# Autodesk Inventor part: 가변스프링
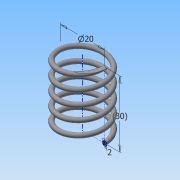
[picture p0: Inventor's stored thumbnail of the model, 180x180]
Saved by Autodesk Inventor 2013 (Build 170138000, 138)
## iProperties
Created: 2019-01
Part Number: 가변스프링
Material: Generic
Document SubType Name: Modeling
Designer: Administrator
Density: 1 g/cm^3
Author: Administrator
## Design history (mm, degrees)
sketch "스케치1"
  geometry: L1 (0, 0)-(10, 0); L2 (10, 0)-(10, 18.7); L3 (10, 18.7)-(0, 18.7); L4 (0, 18.7)-(0, 0); C1 r 1 at (10, 0)
  constraints: 8 end point, 2 parallel, 1 centre point, 1 coincident, 1 horizontal, 1 perpendicular
  dimensions: "d0" = 20 diameter of L2 L4; "d2" = 18.7 distance of L1.end L2.end (derived); "d3" = 2 diameter of C1
feature "코일1" pitch "d4" = 10; turns "d6" = 5; dims "d5" = 18.7 (= d2), "d7" = 0, angle "d8" = 90 deg, angle "d9" = 90 deg, "d10" = 0, "d11" = 0
sketch "스케치2"
  geometry: L1 (-11, 0)-(-9, 0) reference; 1 further point
  constraints: 1 horizontal alignment
extrude "돌출1" cut sketch "스케치2" distance "d12" = 10; taper "d13" = 0 deg
node "작업 평면1"
sketch "스케치3"
  geometry: L1 (1, 0)-(-1, 0) reference; 1 further point
  constraints: 1 horizontal alignment
extrude "돌출2" cut sketch "스케치3" distance "d15" = 10; taper "d16" = 0 deg
node "솔리드1"
node "절단 모서리 투영1"
node "절단 모서리 투영2"
other parameters: "d14" = 90 deg
